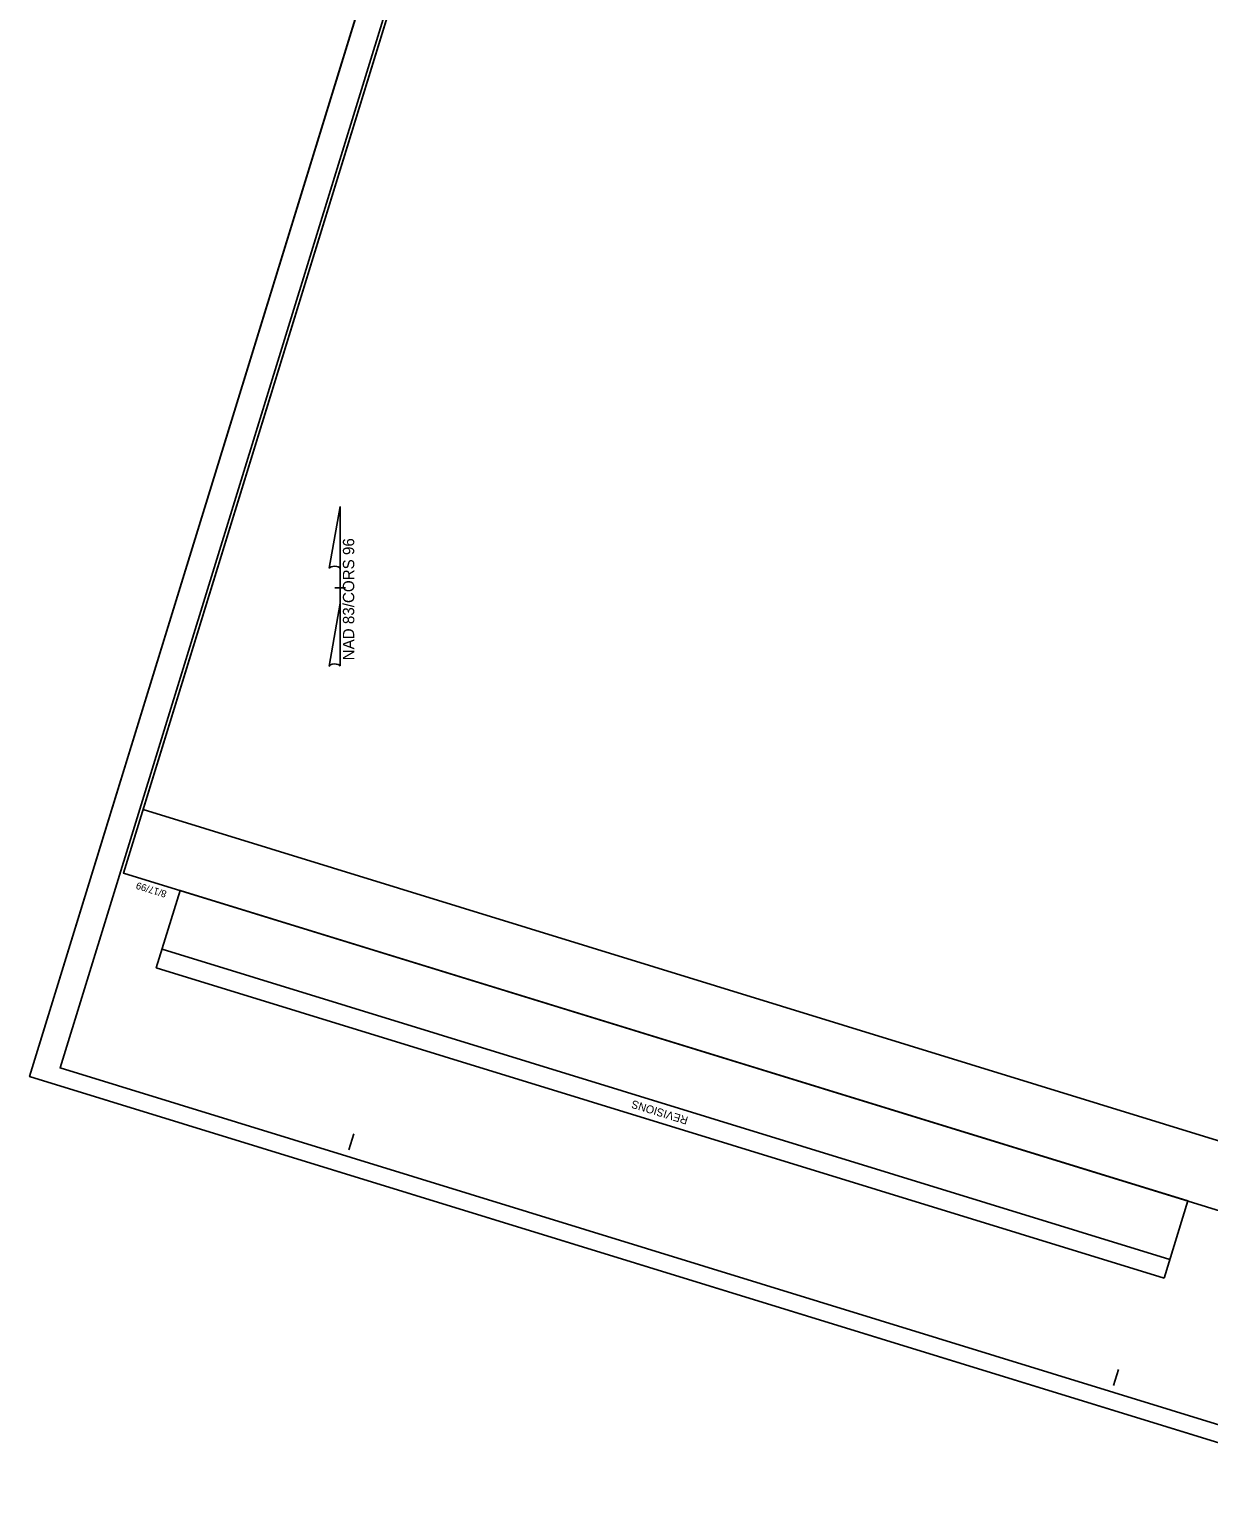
# Model space of a CAD drawing. Extents: x 1347957 to 1349499, y 1028289 to 1030503.
# Drawn here: x 1347957 to 1348841, y 1028289 to 1029396 of the extents above; entities that cross this region are included whole.
import ezdxf

# ---------------------------------------------------------------- set-up
doc = ezdxf.new("R2010")
doc.units = 0
for name, color, linetype in [('Prop North Arrow NAD83 for Plan Sheets CELL', 7, 'Continuous'), ('Sheet Block Revision CELL', 7, 'Continuous'), ('Sheet Clip Boundary CELL', 7, 'Continuous'), ('Sheet Cutting Line CELL', 7, 'Continuous'), ('Sheet Layout Plan Border', 7, 'Continuous'), ('Sheet Plan CELL', 7, 'Continuous'), ('Sheet Plan Layout CELL', 7, 'Continuous'), ('Sheet Plot Border Inside CELL', 7, 'Continuous'), ('Sheet Plot Border Outside CELL', 7, 'Continuous')]:
    doc.layers.add(name, color=color, linetype=linetype)

msp = doc.modelspace()

# ---------------------------------------------------------------- linework, layer by layer
at = {"layer": 'Prop North Arrow NAD83 for Plan Sheets CELL'}
for p, q in [((1348181.7, 1028992.2), (1348189.9, 1029038.5)), ((1348190, 1029038.5), (1348189.9, 1029038.5)), ((1348190, 1029038.5), (1348189.9, 1029038.5)), ((1348190, 1029038.5), (1348190, 1028990.7)), ((1348190, 1028965.9), (1348190, 1028992.1)), ((1348190, 1028990.7), (1348190, 1028992.1)), ((1348186, 1028977.5), (1348185.9, 1028977.5)), ((1348186, 1028977.5), (1348194, 1028977.5)), ((1348189.5, 1028977.5), (1348186, 1028977.5)), ((1348190, 1028965.9), (1348181.6, 1028918.7)), ((1348190, 1028918.9), (1348190, 1028965.9))]:
    msp.add_line(p, q, dxfattribs=at)
for centre, start_param, end_param in [((1348185.9, 1028991.7), 0.216388, 2.908219), ((1348185.9, 1028918.5), 0.201328, 3.141593)]:
    msp.add_ellipse(centre, major_axis=(4.23, -0.03), ratio=0.461098, start_param=start_param, end_param=end_param, dxfattribs=at)
at = {"layer": 'Sheet Block Revision CELL'}
msp.add_line((1348812, 1028473.9), (1348056.4, 1028706.6), dxfattribs=at)
msp.add_lwpolyline([(1348807.8, 1028460), (1348052.1, 1028692.7), (1348069.9, 1028750.5), (1348825.6, 1028517.8)], close=True, dxfattribs=at)
at = {"layer": 'Sheet Clip Boundary CELL'}
msp.add_lwpolyline([(1349045.8, 1028502.3), (1349457.8, 1029840.3), (1348656.4, 1030087.1), (1348600.7, 1029906.2), (1348398.6, 1029968.5), (1348042.3, 1028811.4)], close=True, dxfattribs=at)
at = {"layer": 'Sheet Cutting Line CELL'}
for p, q in [((1348452.5, 1030220), (1347957.1, 1028611.1)), ((1347957.1, 1028611.1), (1349003.6, 1028288.8))]:
    msp.add_line(p, q, dxfattribs=at)
at = {"layer": 'Sheet Layout Plan Border'}
msp.add_lwpolyline([(1349045.8, 1028502.3), (1349457.8, 1029840.3), (1348656.4, 1030087.1), (1348600.7, 1029906.2), (1348398.6, 1029968.5), (1348042.3, 1028811.4)], close=True, dxfattribs=at)
at = {"layer": 'Sheet Plan CELL'}
for p, q in [((1348027.5, 1028763.6), (1348027.5, 1028763.6)), ((1348196.5, 1028556.2), (1348200.2, 1028568.1)), ((1348769.9, 1028379.6), (1348773.6, 1028391.5))]:
    msp.add_line(p, q, dxfattribs=at)
for points in [[(1348469, 1030197.2), (1348027.5, 1028763.6), (1349031, 1028454.5), (1349472.5, 1029888.1)], [(1349031, 1028454.5), (1348027.6, 1028763.5), (1348410.1, 1030006), (1348553.6, 1029961.8), (1348612.4, 1030153), (1349472.5, 1029888.1)]]:
    msp.add_lwpolyline(points, close=True, dxfattribs=at)
at = {"layer": 'Sheet Plan Layout CELL'}
msp.add_lwpolyline([(1348027.6, 1028763.5), (1349031, 1028454.5), (1349472.5, 1029888.1), (1348671.1, 1030134.9), (1348600.7, 1029906.2), (1348398.6, 1029968.5)], close=True, dxfattribs=at)
at = {"layer": 'Sheet Plot Border Inside CELL'}
msp.add_lwpolyline([(1348988.3, 1028307.1), (1349478.6, 1029899.3), (1348470.3, 1030209.8), (1347980, 1028617.6)], close=True, dxfattribs=at)
at = {"layer": 'Sheet Plot Border Outside CELL'}
msp.add_lwpolyline([(1349003.6, 1028288.8), (1349499, 1029897.7), (1348452.5, 1030220), (1347957.1, 1028611.1)], close=True, dxfattribs=at)

# ---------------------------------------------------------------- texts
at = {"layer": 'Prop North Arrow NAD83 for Plan Sheets CELL'}
msp.add_text('NAD 83/CORS 96', height=8.5, rotation=90, dxfattribs=at).set_placement((1348200.5, 1028923.1))
at = {"layer": 'Sheet Block Revision CELL'}
msp.add_text('REVISIONS', height=6, rotation=162.8834, dxfattribs=at).set_placement((1348451.3, 1028580.7))
at = {"layer": 'Sheet Plan CELL'}
msp.add_text('8/17/99', height=5.25, rotation=162.8834, dxfattribs=at).set_placement((1348060.3, 1028750.1))

doc.saveas('drawing.dxf')
